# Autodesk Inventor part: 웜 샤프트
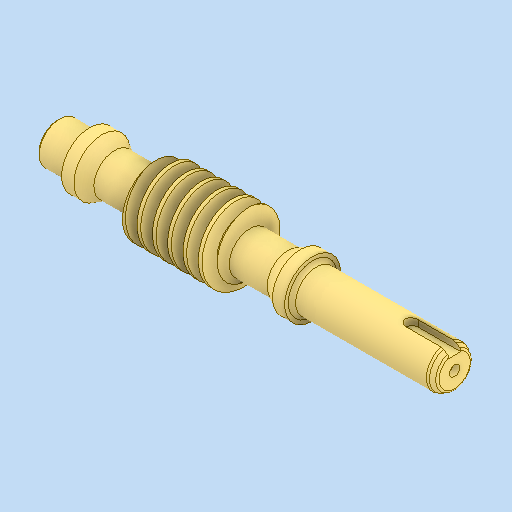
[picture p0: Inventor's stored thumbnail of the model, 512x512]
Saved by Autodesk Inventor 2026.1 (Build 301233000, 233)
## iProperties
Created: 2026-01
Part Number: 웜 샤프트
Material: 강철, 합금
Document SubType Name: Modeling
Designer: PC-30
Density: 7.73 g/cm^3
Appearance: 기본값
Author: jhkim
Sending System: Autodesk Inventor 2026
Preprocessor: ST-DEVELOPER v20.1
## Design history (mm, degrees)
feature "솔리드1"
node "솔리드2"
